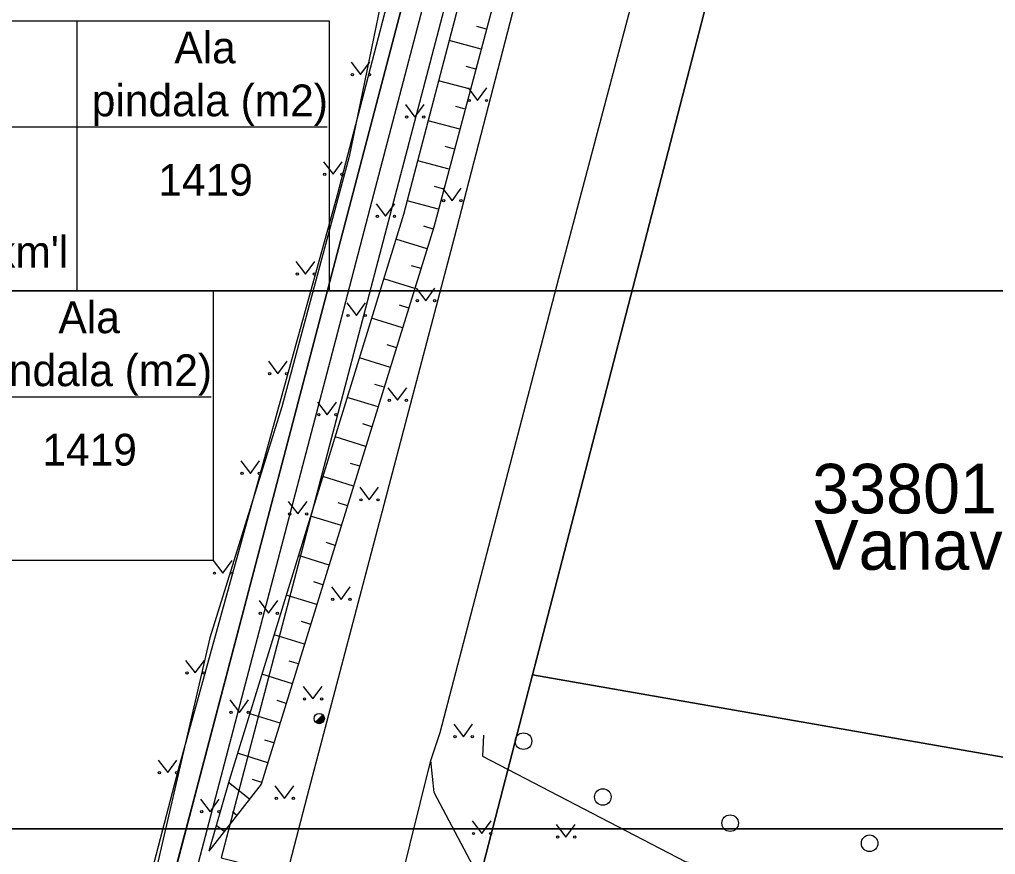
# Model space of a CAD drawing. Extents: x 554947 to 555436, y 6564938 to 6565792.
# Drawn here: x 555148.42 to 555195.59, y 6565157.67 to 6565198.02 of the extents above; entities that cross this region are included whole.
import ezdxf

# ---------------------------------------------------------------- set-up
doc = ezdxf.new("R2010")
doc.units = 0
for name, color, linetype in [('AED', 7, 'Continuous'), ('HALJASTUS', 7, 'Continuous'), ('KASUTUSALA', 7, 'Continuous'), ('KPKAABEL', 7, 'Continuous'), ('PIIR', 7, 'Continuous'), ('POST', 7, 'Continuous'), ('PR_SIDE', 7, 'Continuous'), ('RELJEEF', 7, 'Continuous'), ('TEE', 7, 'Continuous'), ('VORMISTUS', 7, 'Continuous'), ('VORMISTUS_1', 7, 'Continuous')]:
    doc.layers.add(name, color=color, linetype=linetype)

msp = doc.modelspace()

# ---------------------------------------------------------------- linework, layer by layer
at = {"layer": 'AED'}
msp.add_lwpolyline([(555179.37, 6565300.078), (555180.242, 6565299.846), (555180.75, 6565290.874), (555180.137, 6565280.616), (555178.982, 6565264.788), (555177.984, 6565255.288), (555177.306, 6565249.05), (555173.486, 6565227.422), (555169.733, 6565212.423), (555163.779, 6565189.534), (555156.086, 6565161.758), (555151.428, 6565143.905), (555146.995, 6565125.891), (555142.273, 6565107.514), (555136.767, 6565086.759), (555131.214, 6565064.984), (555128.386, 6565056.617), (555127.142, 6565056.522)], dxfattribs=at)
at = {"layer": 'HALJASTUS'}
for p, q in [((555164.444, 6565195.969), (555164.908, 6565195.362)), ((555164.908, 6565195.362), (555165.353, 6565195.969)), ((555170.1, 6565194.717), (555170.563, 6565194.11)), ((555170.563, 6565194.11), (555171.009, 6565194.717)), ((555167.068, 6565193.916), (555167.531, 6565193.309)), ((555167.531, 6565193.309), (555167.977, 6565193.916)), ((555163.112, 6565191.149), (555163.575, 6565190.543)), ((555163.575, 6565190.543), (555164.021, 6565191.149)), ((555168.86, 6565189.873), (555169.324, 6565189.266)), ((555169.324, 6565189.266), (555169.769, 6565189.873)), ((555165.653, 6565189.12), (555166.117, 6565188.513)), ((555166.117, 6565188.513), (555166.562, 6565189.12)), ((555161.78, 6565186.33), (555162.243, 6565185.723)), ((555162.243, 6565185.723), (555162.689, 6565186.33)), ((555167.591, 6565185.037), (555168.055, 6565184.43)), ((555168.055, 6565184.43), (555168.5, 6565185.037)), ((555164.239, 6565184.324), (555164.703, 6565183.718)), ((555164.703, 6565183.718), (555165.148, 6565184.324)), ((555160.448, 6565181.511), (555160.911, 6565180.904)), ((555160.911, 6565180.904), (555161.357, 6565181.511)), ((555166.227, 6565180.227), (555166.69, 6565179.62)), ((555166.69, 6565179.62), (555167.136, 6565180.227)), ((555162.825, 6565179.528), (555163.289, 6565178.922)), ((555163.289, 6565178.922), (555163.734, 6565179.528)), ((555159.116, 6565176.691), (555159.579, 6565176.085)), ((555159.579, 6565176.085), (555160.025, 6565176.691)), ((555164.862, 6565175.417), (555165.325, 6565174.81)), ((555165.325, 6565174.81), (555165.771, 6565175.417)), ((555161.411, 6565174.733), (555161.874, 6565174.126)), ((555161.874, 6565174.126), (555162.32, 6565174.733)), ((555157.784, 6565171.872), (555158.247, 6565171.265)), ((555158.247, 6565171.265), (555158.693, 6565171.872)), ((555163.497, 6565170.606), (555163.961, 6565170)), ((555163.961, 6565170), (555164.406, 6565170.606)), ((555159.997, 6565169.937), (555160.46, 6565169.33)), ((555160.46, 6565169.33), (555160.906, 6565169.937)), ((555156.451, 6565167.053), (555156.915, 6565166.446)), ((555156.915, 6565166.446), (555157.36, 6565167.053)), ((555162.132, 6565165.796), (555162.596, 6565165.19)), ((555162.596, 6565165.19), (555163.041, 6565165.796)), ((555158.583, 6565165.141), (555159.046, 6565164.534)), ((555159.046, 6565164.534), (555159.492, 6565165.141)), ((555169.409, 6565163.97), (555169.872, 6565163.363)), ((555169.872, 6565163.363), (555170.318, 6565163.97)), ((555155.119, 6565162.234), (555155.583, 6565161.627)), ((555155.583, 6565161.627), (555156.028, 6565162.234)), ((555160.768, 6565160.986), (555161.231, 6565160.379)), ((555161.231, 6565160.379), (555161.677, 6565160.986)), ((555157.169, 6565160.345), (555157.632, 6565159.738)), ((555157.632, 6565159.738), (555158.078, 6565160.345)), ((555170.299, 6565159.291), (555170.762, 6565158.685)), ((555170.762, 6565158.685), (555171.208, 6565159.291)), ((555174.364, 6565159.116), (555174.827, 6565158.509)), ((555174.827, 6565158.509), (555175.273, 6565159.116))]:
    msp.add_line(p, q, dxfattribs=at)
msp.add_lwpolyline([(555170.849, 6565163.433), (555170.802, 6565162.422), (555180.588, 6565157.338), (555194.166, 6565154.476), (555200.547, 6565151.934), (555210.105, 6565148.383), (555222.421, 6565148.556), (555228.239, 6565151.421), (555231.104, 6565153.786)], dxfattribs=at)
for centre, radius in [((555164.507, 6565195.362), 0.055), ((555165.335, 6565195.362), 0.055), ((555170.162, 6565194.11), 0.055), ((555170.991, 6565194.11), 0.055), ((555167.13, 6565193.309), 0.055), ((555167.959, 6565193.309), 0.055), ((555163.174, 6565190.543), 0.055), ((555164.003, 6565190.543), 0.055), ((555168.923, 6565189.266), 0.055), ((555169.752, 6565189.266), 0.055), ((555165.716, 6565188.513), 0.055), ((555166.545, 6565188.513), 0.055), ((555161.842, 6565185.723), 0.055), ((555162.671, 6565185.723), 0.055), ((555167.654, 6565184.43), 0.055), ((555168.483, 6565184.43), 0.055), ((555164.302, 6565183.718), 0.055), ((555165.13, 6565183.718), 0.055), ((555160.51, 6565180.904), 0.055), ((555161.339, 6565180.904), 0.055), ((555166.289, 6565179.62), 0.055), ((555167.118, 6565179.62), 0.055), ((555162.888, 6565178.922), 0.055), ((555163.716, 6565178.922), 0.055), ((555159.178, 6565176.085), 0.055), ((555160.007, 6565176.085), 0.055), ((555164.924, 6565174.81), 0.055), ((555165.753, 6565174.81), 0.055), ((555161.473, 6565174.126), 0.055), ((555162.302, 6565174.126), 0.055), ((555157.846, 6565171.265), 0.055), ((555158.675, 6565171.265), 0.055), ((555163.559, 6565170), 0.055), ((555164.388, 6565170), 0.055), ((555160.059, 6565169.33), 0.055), ((555160.888, 6565169.33), 0.055), ((555156.514, 6565166.446), 0.055), ((555157.343, 6565166.446), 0.055), ((555162.195, 6565165.19), 0.055), ((555163.024, 6565165.19), 0.055), ((555158.645, 6565164.534), 0.055), ((555159.474, 6565164.534), 0.055), ((555169.471, 6565163.363), 0.055), ((555170.3, 6565163.363), 0.055), ((555172.778, 6565163.146), 0.4), ((555155.182, 6565161.627), 0.055), ((555156.01, 6565161.627), 0.055), ((555176.613, 6565160.448), 0.4), ((555160.83, 6565160.379), 0.055), ((555161.659, 6565160.379), 0.055), ((555157.231, 6565159.738), 0.055), ((555158.06, 6565159.738), 0.055), ((555182.764, 6565159.183), 0.4), ((555170.361, 6565158.685), 0.055), ((555171.19, 6565158.685), 0.055), ((555174.426, 6565158.509), 0.055), ((555175.255, 6565158.509), 0.055), ((555189.505, 6565158.213), 0.4)]:
    msp.add_circle(centre, radius, dxfattribs=at)
at = {"layer": 'KASUTUSALA'}
for points in [[(555127.058, 6565046.777), (555141.002, 6565099.93), (555152.728, 6565144.628), (555155.084, 6565153.611), (555155.888, 6565156.675), (555156.912, 6565160.576), (555162.414, 6565181.549), (555172.651, 6565220.574), (555172.7, 6565220.76), (555176.927, 6565240.07), (555176.937, 6565240.135), (555179.22, 6565254.85)], [(555181.208, 6565254.618), (555178.897, 6565239.723), (555174.645, 6565220.292), (555158.175, 6565157.509), (555170.133, 6565154.484), (555169.631, 6565152.548), (555157.917, 6565155.511), (555157.606, 6565155.409), (555157.1, 6565153.341), (555146.607, 6565113.414), (555140.881, 6565091.587), (555138.365, 6565081.691), (555135.803, 6565072.229), (555119.022, 6565008.261)]]:
    msp.add_lwpolyline(points, dxfattribs=at)
at = {"layer": 'KPKAABEL'}
msp.add_lwpolyline([(555172.536, 6565254.014), (555171.281, 6565241.464), (555170.488, 6565231.192), (555168.866, 6565217.1), (555167.048, 6565204.461), (555164.351, 6565191.399), (555161.107, 6565179.306), (555157.628, 6565168.142), (555155.008, 6565156.873), (555154.465, 6565156.331), (555152.85, 6565155.986), (555149.5, 6565156.323)], dxfattribs=at)
at = {"layer": 'PIIR'}
msp.add_lwpolyline([(554962.55, 6565234.93), (555180.26, 6565306.43), (555180.8, 6565287.7), (555180.41, 6565269.99), (555179.22, 6565254.85), (555176.93, 6565240.09), (555172.7, 6565220.76), (555117.14, 6565008.97), (555108.27, 6564991.27)], close=True, dxfattribs=at)
for points in [[(555293.54, 6565286.23), (555256.63, 6565245.54), (555254.61, 6565228.5), (555255.75, 6565226.79), (555261.42, 6565218.27), (555289.11, 6565186.6), (555315.28, 6565149.09), (555315.73, 6565134.86), (555310.07, 6565124.47), (555303.59, 6565115.89), (555291.54, 6565100.48), (555288.85, 6565092.31), (555275.41, 6565088.83), (555273.15, 6565087.34), (555239.11, 6565139), (555231.12, 6565150.64), (555225.89, 6565157.13), (555173.21, 6565166.35), (555173.84, 6565168.77), (555191.64, 6565237.48), (555195.28, 6565271.63)], [(555195.28, 6565271.63), (555191.64, 6565237.48), (555173.84, 6565168.77), (555173.21, 6565166.35), (555172.58, 6565163.93), (555140.74, 6565041.04), (555133.32, 6565012.53), (555119.68, 6564972.95), (555107.79, 6564965.53), (555093.78, 6564958.98), (555080.97, 6564954.71), (555029.586, 6564944.201)], [(555029.586, 6564962.189), (555076.32, 6564971.61), (555087.28, 6564975.26), (555098.22, 6564980.37), (555106.03, 6564987.06), (555108.27, 6564991.27), (555117.14, 6565008.97), (555172.7, 6565220.76), (555176.93, 6565240.09), (555179.22, 6565254.85)], [(555272.013, 6565013.369), (555140.74, 6565041.04), (555172.58, 6565163.93), (555173.21, 6565166.35), (555225.89, 6565157.13), (555231.12, 6565150.64), (555239.11, 6565139), (555273.15, 6565087.34), (555275.41, 6565088.83), (555288.85, 6565092.31), (555289.83, 6565088.53), (555290.166, 6565088.221)]]:
    msp.add_lwpolyline(points, dxfattribs=at)
at = {"layer": 'POST'}
msp.add_line((555162.73, 6565164.063), (555163.084, 6565164.417), dxfattribs=at)
msp.add_circle((555162.907, 6565164.24), 0.25, dxfattribs=at)
for radius, start, end in [(0.225, 224.8541, 45.0356), (0.2, 224.8427, 45.047), (0.175, 224.8281, 45.0616), (0.15, 224.8087, 45.081), (0.125, 224.7814, 45.1083), (0.1, 224.7406, 45.1491), (0.075, 224.6725, 45.2172), (0.05, 224.5363, 45.3534), (0.025, 224.1278, 45.7619)]:
    msp.add_arc((555162.907, 6565164.24), radius, start, end, dxfattribs=at)
at = {"layer": 'PR_SIDE'}
msp.add_lwpolyline([(555210.992, 6564988.671), (555132.015, 6564980.717), (555127.536, 6564982.26), (555122.65, 6564985.013), (555110.837, 6564991.67), (555110.25, 6564992.989), (555118.081, 6565008.615), (555124.872, 6565034.501), (555128.062, 6565046.662), (555134.837, 6565072.487), (555137.397, 6565081.944), (555139.913, 6565091.837), (555145.64, 6565113.668), (555156.083, 6565153.408), (555155.859, 6565155.17), (555156.452, 6565155.519), (555156.834, 6565156.34), (555160.763, 6565171.317), (555163.707, 6565182.54), (555165.376, 6565188.901), (555173.672, 6565220.526), (555176.862, 6565235.1), (555177.913, 6565239.906), (555180.214, 6565254.734)], dxfattribs=at)
at = {"layer": 'RELJEEF'}
for p, q in [((555170.991, 6565197.557), (555170.525, 6565197.681)), ((555170.734, 6565196.591), (555169.184, 6565197.003)), ((555170.477, 6565195.624), (555170.013, 6565195.748)), ((555170.22, 6565194.658), (555168.678, 6565195.068)), ((555169.963, 6565193.692), (555169.501, 6565193.814)), ((555169.706, 6565192.725), (555168.171, 6565193.134)), ((555169.449, 6565191.759), (555168.989, 6565191.881)), ((555169.192, 6565190.792), (555167.664, 6565191.199)), ((555168.934, 6565189.826), (555168.477, 6565189.948)), ((555168.677, 6565188.86), (555167.157, 6565189.264)), ((555168.417, 6565187.894), (555167.964, 6565188.034)), ((555168.121, 6565186.939), (555166.615, 6565187.406)), ((555167.825, 6565185.984), (555167.373, 6565186.124)), ((555167.529, 6565185.029), (555166.026, 6565185.495)), ((555167.233, 6565184.074), (555166.782, 6565184.213)), ((555166.937, 6565183.118), (555165.436, 6565183.583)), ((555166.641, 6565182.163), (555166.191, 6565182.303)), ((555166.345, 6565181.208), (555164.847, 6565181.672)), ((555166.049, 6565180.253), (555165.6, 6565180.392)), ((555165.753, 6565179.298), (555164.258, 6565179.761)), ((555165.457, 6565178.342), (555165.009, 6565178.481)), ((555165.161, 6565177.387), (555163.669, 6565177.849)), ((555164.865, 6565176.432), (555164.418, 6565176.571)), ((555164.569, 6565175.477), (555163.08, 6565175.938)), ((555164.273, 6565174.522), (555163.826, 6565174.66)), ((555163.977, 6565173.567), (555162.491, 6565174.027)), ((555163.681, 6565172.611), (555163.235, 6565172.749)), ((555163.385, 6565171.656), (555161.902, 6565172.116)), ((555163.089, 6565170.701), (555162.644, 6565170.839)), ((555162.793, 6565169.746), (555161.313, 6565170.204)), ((555162.497, 6565168.791), (555162.053, 6565168.928)), ((555162.201, 6565167.835), (555160.724, 6565168.293)), ((555161.905, 6565166.88), (555161.462, 6565167.017)), ((555161.609, 6565165.925), (555160.135, 6565166.382)), ((555161.313, 6565164.97), (555160.871, 6565165.107)), ((555161.016, 6565164.015), (555159.546, 6565164.471)), ((555160.72, 6565163.06), (555160.28, 6565163.196)), ((555160.424, 6565162.104), (555158.957, 6565162.559)), ((555159.54, 6565160.347), (555158.523, 6565161.146)), ((555160.128, 6565161.149), (555159.689, 6565161.286)), ((555158.923, 6565159.561), (555158.713, 6565159.725)), ((555158.305, 6565158.774), (555157.926, 6565159.072)), ((555157.688, 6565157.987), (555157.67, 6565158.002))]:
    msp.add_line(p, q, dxfattribs=at)
for points in [[(555184.566, 6565294.895), (555185.953, 6565280.072), (555185.143, 6565263.746), (555184.046, 6565254.819), (555183.226, 6565249.112), (555179.005, 6565228.311), (555174.467, 6565210.622), (555168.444, 6565187.982), (555160.102, 6565161.063), (555157.57, 6565157.837)], [(555184.566, 6565294.895), (555182.784, 6565279.965), (555183.347, 6565264.524), (555181.678, 6565255.565), (555181.412, 6565249.474), (555177.118, 6565228.691), (555172.906, 6565211.208), (555166.985, 6565188.606), (555158.553, 6565161.251), (555157.57, 6565157.837)]]:
    msp.add_lwpolyline(points, dxfattribs=at)
at = {"layer": 'TEE'}
for points in [[(555183.594, 6565248.995), (555179.697, 6565227.862), (555175.388, 6565210.507), (555169.433, 6565187.479), (555162.32, 6565160.507), (555157.772, 6565142.96), (555152.674, 6565123.751), (555148.003, 6565106.069), (555142.307, 6565084.705), (555136.784, 6565063.937), (555131.82, 6565044.704), (555126.529, 6565024.437), (555123.003, 6565010.821), (555119.083, 6564999.093), (555116.16, 6564993.195), (555108.256, 6564982.259)], [(555114.997, 6564980.207), (555119.473, 6564986.791), (555121.429, 6564990.442), (555124.132, 6564996.667), (555128.448, 6565009.121), (555131.982, 6565022.769), (555137.234, 6565043.213), (555142.087, 6565062.036), (555147.465, 6565082.979), (555153.125, 6565104.459), (555157.981, 6565122.311), (555163.2, 6565141.618), (555168.3, 6565162.209), (555168.744, 6565163.563), (555174.483, 6565185.521), (555180.709, 6565208.971), (555185.087, 6565226.838), (555186.799, 6565233.51), (555187.911, 6565235.651)], [(555205.86, 6565133.779), (555206.217, 6565135.824), (555207.407, 6565138.329), (555209.429, 6565140.104), (555211.794, 6565141.192), (555217.229, 6565143.067), (555216.442, 6565145.526), (555210.771, 6565144.283), (555206.511, 6565143.557), (555202.006, 6565143.277), (555191.831, 6565146.626), (555179.65, 6565150.043), (555174.155, 6565151.803), (555172.54, 6565153.141), (555170.207, 6565157.377), (555168.463, 6565160.669), (555168.3, 6565162.209)]]:
    msp.add_lwpolyline(points, dxfattribs=at)
at = {"layer": 'VORMISTUS'}
msp.add_line((555052.086, 6565179.793), (555157.686, 6565179.793), dxfattribs=at)
for points in [[(555217.086, 6564974.913), (555052.086, 6564974.913), (555052.086, 6565184.913), (555217.086, 6565184.913)], [(555052.086, 6565184.913), (555157.784, 6565184.913), (555157.784, 6565171.872), (555052.086, 6565171.872)]]:
    msp.add_lwpolyline(points, close=True, dxfattribs=at)
at = {"layer": 'VORMISTUS_1'}
for p, q in [((555151.19, 6565197.954), (555151.19, 6565184.913)), ((555151.19, 6565197.954), (555151.19, 6565184.913)), ((555057.688, 6565192.834), (555163.288, 6565192.834))]:
    msp.add_line(p, q, dxfattribs=at)
for points in [[(555045.188, 6565158.913), (555235.188, 6565158.913), (555235.188, 6565433.913), (555045.188, 6565433.913)], [(555045.188, 6565433.913), (555235.188, 6565433.913), (555235.188, 6565158.913), (555045.188, 6565158.913)], [(555222.688, 6565184.913), (555057.688, 6565184.913), (555057.688, 6565394.913), (555222.688, 6565394.913)], [(555057.688, 6565197.954), (555163.385, 6565197.954), (555163.385, 6565184.913), (555057.688, 6565184.913)]]:
    msp.add_lwpolyline(points, close=True, dxfattribs=at)

# ---------------------------------------------------------------- texts
at = {"layer": 'PIIR'}
for s, p in [('33801:001:0390', (555186.732, 6565174.152)), ('Vanaveski', (555186.834, 6565171.429))]:
    msp.add_text(s, height=2.4, dxfattribs=at).set_placement(p)
at = {"layer": 'VORMISTUS'}
for s, p in [('Ala', (555150.304, 6565182.865)), ('pindala (m2)', (555146.312, 6565180.305)), ('1419', (555149.527, 6565176.465))]:
    msp.add_text(s, height=1.536, dxfattribs=at).set_placement(p)
at = {"layer": 'VORMISTUS_1'}
for s, p in [('Ala', (555155.905, 6565195.906)), ('pindala (m2)', (555151.913, 6565193.346)), ('1419', (555155.128, 6565189.506)), ("ristumine 13,63; 13,73 ja 13,91 km'l", (555118.421, 6565186.027))]:
    msp.add_text(s, height=1.536, dxfattribs=at).set_placement(p)

doc.saveas('drawing.dxf')
